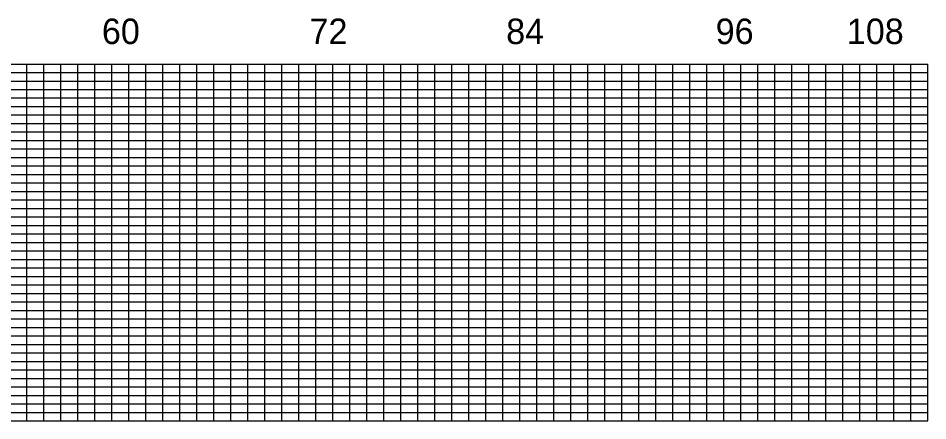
# Model space of a CAD drawing. Extents: x 1873632 to 1926512, y 813126 to 836257.
# Drawn here: x 1886338 to 1889013, y 817984 to 819168 of the extents above; entities that cross this region are included whole.
import ezdxf

# ---------------------------------------------------------------- set-up
doc = ezdxf.new("R2010")
doc.units = 0
doc.layers.add('RD_PD_WallFill', color=7, linetype='Continuous')

msp = doc.modelspace()

# ---------------------------------------------------------------- linework, layer by layer
at = {"layer": 'RD_PD_WallFill'}
for p, q in [((1883663.1, 819033.6), (1889013.1, 819033.6)), ((1886363.1, 817983.6), (1886363.1, 819033.6)), ((1886363.1, 817983.6), (1886363.1, 819033.6)), ((1886413.1, 817983.6), (1886413.1, 819033.6)), ((1886413.1, 817983.6), (1886413.1, 819033.6)), ((1886463.1, 817983.6), (1886463.1, 819033.6)), ((1886463.1, 817983.6), (1886463.1, 819033.6)), ((1886513.1, 817983.6), (1886513.1, 819033.6)), ((1886513.1, 817983.6), (1886513.1, 819033.6)), ((1886563.1, 817983.6), (1886563.1, 819033.6)), ((1886563.1, 817983.6), (1886563.1, 819033.6)), ((1886613.1, 817983.6), (1886613.1, 819033.6)), ((1886613.1, 817983.6), (1886613.1, 819033.6)), ((1886663.1, 817983.6), (1886663.1, 819033.6)), ((1886663.1, 817983.6), (1886663.1, 819033.6)), ((1886713.1, 817983.6), (1886713.1, 819033.6)), ((1886713.1, 817983.6), (1886713.1, 819033.6)), ((1886763.1, 817983.6), (1886763.1, 819033.6)), ((1886763.1, 817983.6), (1886763.1, 819033.6)), ((1886813.1, 817983.6), (1886813.1, 819033.6)), ((1886813.1, 817983.6), (1886813.1, 819033.6)), ((1886863.1, 817983.6), (1886863.1, 819033.6)), ((1886863.1, 817983.6), (1886863.1, 819033.6)), ((1886913.1, 817983.6), (1886913.1, 819033.6)), ((1886913.1, 817983.6), (1886913.1, 819033.6)), ((1886963.1, 817983.6), (1886963.1, 819033.6)), ((1886963.1, 817983.6), (1886963.1, 819033.6)), ((1887013.1, 817983.6), (1887013.1, 819033.6)), ((1887013.1, 817983.6), (1887013.1, 819033.6)), ((1887063.1, 817983.6), (1887063.1, 819033.6)), ((1887063.1, 817983.6), (1887063.1, 819033.6)), ((1887113.1, 817983.6), (1887113.1, 819033.6)), ((1887113.1, 817983.6), (1887113.1, 819033.6)), ((1887163.1, 817983.6), (1887163.1, 819033.6)), ((1887163.1, 817983.6), (1887163.1, 819033.6)), ((1887213.1, 817983.6), (1887213.1, 819033.6)), ((1887213.1, 817983.6), (1887213.1, 819033.6)), ((1887263.1, 817983.6), (1887263.1, 819033.6)), ((1887263.1, 817983.6), (1887263.1, 819033.6)), ((1887313.1, 817983.6), (1887313.1, 819033.6)), ((1887313.1, 817983.6), (1887313.1, 819033.6)), ((1887363.1, 817983.6), (1887363.1, 819033.6)), ((1887363.1, 817983.6), (1887363.1, 819033.6)), ((1887413.1, 817983.6), (1887413.1, 819033.6)), ((1887413.1, 817983.6), (1887413.1, 819033.6)), ((1887463.1, 817983.6), (1887463.1, 819033.6)), ((1887463.1, 817983.6), (1887463.1, 819033.6)), ((1887513.1, 817983.6), (1887513.1, 819033.6)), ((1887513.1, 817983.6), (1887513.1, 819033.6)), ((1887563.1, 817983.6), (1887563.1, 819033.6)), ((1887563.1, 817983.6), (1887563.1, 819033.6)), ((1887613.1, 817983.6), (1887613.1, 819033.6)), ((1887613.1, 817983.6), (1887613.1, 819033.6)), ((1887663.1, 817983.6), (1887663.1, 819033.6)), ((1887663.1, 817983.6), (1887663.1, 819033.6)), ((1887713.1, 817983.6), (1887713.1, 819033.6)), ((1887713.1, 817983.6), (1887713.1, 819033.6)), ((1887763.1, 817983.6), (1887763.1, 819033.6)), ((1887763.1, 817983.6), (1887763.1, 819033.6)), ((1887813.1, 817983.6), (1887813.1, 819033.6)), ((1887813.1, 817983.6), (1887813.1, 819033.6)), ((1887863.1, 817983.6), (1887863.1, 819033.6)), ((1887863.1, 817983.6), (1887863.1, 819033.6)), ((1887913.1, 817983.6), (1887913.1, 819033.6)), ((1887913.1, 817983.6), (1887913.1, 819033.6)), ((1887963.1, 817983.6), (1887963.1, 819033.6)), ((1887963.1, 817983.6), (1887963.1, 819033.6)), ((1888013.1, 817983.6), (1888013.1, 819033.6)), ((1888013.1, 817983.6), (1888013.1, 819033.6)), ((1888063.1, 817983.6), (1888063.1, 819033.6)), ((1888063.1, 817983.6), (1888063.1, 819033.6)), ((1888113.1, 817983.6), (1888113.1, 819033.6)), ((1888113.1, 817983.6), (1888113.1, 819033.6)), ((1888163.1, 817983.6), (1888163.1, 819033.6)), ((1888163.1, 817983.6), (1888163.1, 819033.6)), ((1888213.1, 817983.6), (1888213.1, 819033.6)), ((1888213.1, 817983.6), (1888213.1, 819033.6)), ((1888263.1, 817983.6), (1888263.1, 819033.6)), ((1888263.1, 817983.6), (1888263.1, 819033.6)), ((1888313.1, 817983.6), (1888313.1, 819033.6)), ((1888313.1, 817983.6), (1888313.1, 819033.6)), ((1888363.1, 817983.6), (1888363.1, 819033.6)), ((1888363.1, 817983.6), (1888363.1, 819033.6)), ((1888413.1, 817983.6), (1888413.1, 819033.6)), ((1888413.1, 817983.6), (1888413.1, 819033.6)), ((1888463.1, 817983.6), (1888463.1, 819033.6)), ((1888463.1, 817983.6), (1888463.1, 819033.6)), ((1888513.1, 817983.6), (1888513.1, 819033.6)), ((1888513.1, 817983.6), (1888513.1, 819033.6)), ((1888563.1, 817983.6), (1888563.1, 819033.6)), ((1888563.1, 817983.6), (1888563.1, 819033.6)), ((1888613.1, 817983.6), (1888613.1, 819033.6)), ((1888613.1, 817983.6), (1888613.1, 819033.6)), ((1888663.1, 817983.6), (1888663.1, 819033.6)), ((1888663.1, 817983.6), (1888663.1, 819033.6)), ((1888713.1, 817983.6), (1888713.1, 819033.6)), ((1888713.1, 817983.6), (1888713.1, 819033.6)), ((1888763.1, 817983.7), (1888763.1, 819033.6)), ((1888763.1, 817983.7), (1888763.1, 819033.6)), ((1888813.1, 817983.6), (1888813.1, 819033.6)), ((1888813.1, 817983.6), (1888813.1, 819033.6)), ((1888863.1, 817983.6), (1888863.1, 819033.6)), ((1888863.1, 817983.6), (1888863.1, 819033.6)), ((1888913.1, 817983.6), (1888913.1, 819033.6)), ((1888913.1, 817983.6), (1888913.1, 819033.6)), ((1888963.1, 817983.6), (1888963.1, 819033.6)), ((1888963.1, 817983.6), (1888963.1, 819033.6)), ((1889013.1, 817983.6), (1889013.1, 819033.6)), ((1889013.1, 817983.6), (1889013.1, 819033.6)), ((1884113.1, 819008.6), (1889013.1, 819008.6)), ((1884113.1, 819008.6), (1889013.1, 819008.6)), ((1884113.1, 818983.6), (1889013.1, 818983.6)), ((1884113.1, 818958.6), (1889013.1, 818958.6)), ((1884113.1, 818933.6), (1889013.1, 818933.6)), ((1884113.1, 818908.6), (1889013.1, 818908.6)), ((1883663.1, 818883.6), (1889013.1, 818883.6)), ((1883663.1, 818858.6), (1889013.1, 818858.6)), ((1883663.1, 818833.6), (1889013.1, 818833.6)), ((1883663.1, 818808.6), (1889013.1, 818808.6)), ((1883663.1, 818783.6), (1889013.1, 818783.6)), ((1883663.1, 818758.6), (1889013.1, 818758.6)), ((1883663.1, 818733.6), (1889013.1, 818733.6)), ((1883663.1, 818708.6), (1889013.1, 818708.6)), ((1883663.1, 818683.6), (1889013.1, 818683.6)), ((1883663.1, 818658.6), (1889013.1, 818658.6)), ((1883663.1, 818633.6), (1889013.1, 818633.6)), ((1883663.1, 818608.6), (1889013.1, 818608.6)), ((1883663.1, 818583.6), (1889013.1, 818583.6)), ((1883663.1, 818558.6), (1889013.1, 818558.6)), ((1883663.1, 818533.6), (1889013.1, 818533.6)), ((1883663.1, 818508.6), (1889013.1, 818508.6)), ((1883663.1, 818483.6), (1889013.1, 818483.6)), ((1883663.1, 818458.6), (1889013.1, 818458.6)), ((1883663.1, 818433.6), (1889013.1, 818433.6)), ((1883663.1, 818408.6), (1889013.1, 818408.6)), ((1883663.1, 818383.6), (1889013.1, 818383.6)), ((1883663.1, 818358.6), (1889013.1, 818358.6)), ((1883663.1, 818333.6), (1889013.1, 818333.6)), ((1883663.1, 818308.6), (1889013.1, 818308.6)), ((1883663.1, 818283.6), (1889013.1, 818283.6)), ((1883663.1, 818258.6), (1889013.1, 818258.6)), ((1883663.1, 818233.6), (1889013.1, 818233.6)), ((1883663.1, 818208.6), (1889013.1, 818208.6)), ((1883663.1, 818183.6), (1889013.1, 818183.6)), ((1883663.1, 818158.6), (1889013.1, 818158.6)), ((1883663.1, 818133.6), (1889013.1, 818133.6)), ((1883663.1, 818108.6), (1889013.1, 818108.6)), ((1883663.1, 818083.6), (1889013.1, 818083.6)), ((1883663.1, 818058.6), (1889013.1, 818058.6)), ((1883663.1, 818033.6), (1889013.1, 818033.6)), ((1883663.1, 818008.6), (1889013.1, 818008.6)), ((1883663.1, 817983.6), (1889013.1, 817983.6)), ((1883663.1, 817983.6), (1889013.1, 817983.6))]:
    msp.add_line(p, q, dxfattribs=at)

# ---------------------------------------------------------------- texts
for s, p in [('60', (1886584.3, 819092.3)), ('60', (1886584.3, 819092.3)), ('72', (1887194.9, 819092.3)), ('72', (1887194.9, 819092.3)), ('84', (1887773.2, 819092.3)), ('84', (1887773.2, 819092.3)), ('96', (1888389.3, 819092.3)), ('96', (1888389.3, 819092.3)), ('108', (1888775, 819092.3))]:
    msp.add_text(s, height=75, dxfattribs=at).set_placement(p)

doc.saveas('drawing.dxf')
